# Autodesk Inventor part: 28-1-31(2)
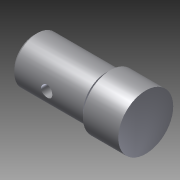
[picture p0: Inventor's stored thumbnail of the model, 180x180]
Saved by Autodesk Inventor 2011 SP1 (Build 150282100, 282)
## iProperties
Created: 2014-01
Part Number: 28-1-31(2)
Document SubType Name: Modeling
Designer: Administrator
Density: 1 g/cm^3
Author: Administrator
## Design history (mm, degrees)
sketch "草图1"
  geometry: L1 (0, 0)-(0, 9); L2 (0, 9)-(1.414, 10.414); L3 (1.414, 10.414)-(32.414, 10.414); L4 (32.414, 10.414)-(32.414, 8.414); L5 (32.414, 8.414)-(34.414, 8.414); L6 (34.414, 8.414)-(34.414, 12.414); L7 (34.414, 12.414)-(50.414, 12.414); L8 (50.414, 12.414)-(50.414, 0); L9 (50.414, 0)-(0, 0)
  constraints: 18 end point, 4 perpendicular, 3 parallel, 1 vertical
  dimensions: "d0" = 9 distance of L1.start L1.end; "d1" = 2 distance of L1.end L2.end; "d2" = 135 deg angle of L1 L2; "d3" = 31 distance of L2.end L3.end; "d4" = 2 distance of L3.end L4.end; "d5" = 2 distance of L4.end L5.end; "d6" = 4 distance of L5.end L6.end; "d7" = 16 distance of L6.end L7.end
revolve "旋转1" sketch "草图1" stored, may be unused: angle "d8" = 90 deg
node "工作平面6"
sketch "草图9"
  geometry: L1 (0, 9)-(0, -9) reference; 2 further points
hole "Hole3" sketch "草图9" at (-16, 0) diameter "d46" = 5.1; stored, may be unused: countersink angle "d50" = 90 deg, drill point angle "d52" = 118 deg; dims "d47" = 6, "d48" = 4, "d49" = 2, "d51" = 8
node "工作平面7"
sketch "草图10"
  geometry: L1 (-20.5, 4.5)-(-11.5, 4.5); L2 (-11.5, 4.5)-(-11.5, -4.5); L3 (-11.5, -4.5)-(-20.5, -4.5); L4 (-20.5, -4.5)-(-20.5, 4.5); 4 further points
  constraints: 8 end point, 1 horizontal alignment, 1 midpoint, 10 other
  dimensions: "d54" = 9 distance of L1.end L2.end
extrude "拉伸4" cut sketch "草图10" distance "d55" = 1; taper "d56" = 0 deg
node "实体1"
other parameters: "d53" = 10.414
